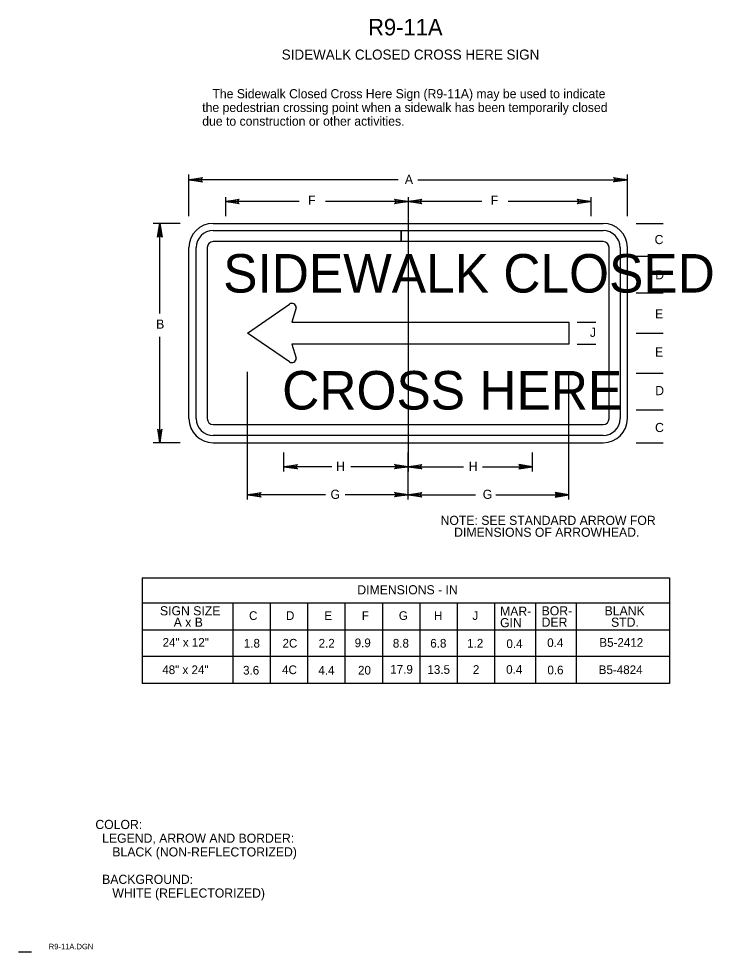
# Model space of a CAD drawing. Extents: x 0.004 to 0.194, y 0.004 to 0.259.
import ezdxf

# ---------------------------------------------------------------- set-up
doc = ezdxf.new("R2010")
doc.units = 0
for name, color, linetype in [('1', 7, 'Continuous'), ('2', 7, 'Continuous'), ('3', 7, 'Continuous'), ('63', 7, 'Continuous')]:
    doc.layers.add(name, color=color, linetype=linetype)

# ---------------------------------------------------------------- blocks, each defined once
blk = doc.blocks.new('RARROW')
at = {"layer": '3'}
for p, q in [((-2.156, 0.28500000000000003), (-2.2665, 0.384625)), ((-2.2665, 0.384625), (0, 0)), ((0, 0), (-2.2665, -0.379125)), ((-2.156, 0.28500000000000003), (-2.075625, 0.12075)), ((0, 0), (-2.156, 0.28500000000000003)), ((-2.14975, -0.2705), (0, 0)), ((-2.075625, 0.12075), (0, 0)), ((0, 0), (-2.074, -0.108)), ((-2.2665, -0.379125), (-2.14975, -0.2705)), ((-2.074, -0.108), (-2.14975, -0.2705))]:
    blk.add_line(p, q, dxfattribs=at)

msp = doc.modelspace()

# ---------------------------------------------------------------- linework, layer by layer
at = {"layer": '1'}
for p, q in [((0.060734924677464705, 0.2103580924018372), (0.060734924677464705, 0.2051699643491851)), ((0.11073492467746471, 0.2103580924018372), (0.11073492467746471, 0.2051699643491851)), ((0.1607349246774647, 0.2103580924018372), (0.1607349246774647, 0.2051699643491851)), ((0.11073492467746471, 0.20747962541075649), (0.11073492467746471, 0.1353943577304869)), ((0.04834544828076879, 0.2032247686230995), (0.040945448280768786, 0.2032247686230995)), ((0.1731244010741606, 0.2032247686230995), (0.18052440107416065, 0.2032247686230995)), ((0.05733492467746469, 0.2012247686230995), (0.10885361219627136, 0.2012247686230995)), ((0.10885361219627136, 0.2012247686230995), (0.10885361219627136, 0.19822476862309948)), ((0.10885361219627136, 0.19822476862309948), (0.10885361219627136, 0.2012247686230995)), ((0.10885361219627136, 0.2012247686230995), (0.16413492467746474, 0.2012247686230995)), ((0.05273492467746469, 0.14982476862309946), (0.05273492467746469, 0.19662476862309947)), ((0.0557349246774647, 0.19662476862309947), (0.0557349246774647, 0.14982476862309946)), ((0.10885361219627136, 0.19822476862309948), (0.05733492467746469, 0.19822476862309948)), ((0.16413492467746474, 0.19822476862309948), (0.10885361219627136, 0.19822476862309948)), ((0.1657349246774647, 0.14982476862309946), (0.1657349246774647, 0.19662476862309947)), ((0.1687349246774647, 0.19662476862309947), (0.1687349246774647, 0.14982476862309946)), ((0.1731244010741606, 0.1942247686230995), (0.18052440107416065, 0.1942247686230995)), ((0.1731244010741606, 0.1842247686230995), (0.18052440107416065, 0.1842247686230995)), ((0.06673492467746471, 0.17322476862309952), (0.07823635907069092, 0.18111449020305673)), ((0.08011521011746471, 0.18012491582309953), (0.07891127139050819, 0.17622483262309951)), ((0.07891127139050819, 0.17622483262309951), (0.15473492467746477, 0.17622483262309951)), ((0.15473492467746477, 0.17622483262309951), (0.15473492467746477, 0.17022470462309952)), ((0.15697181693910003, 0.17622483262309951), (0.16213492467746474, 0.17622483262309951)), ((0.07823635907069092, 0.16533504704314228), (0.06673492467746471, 0.17322476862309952)), ((0.1731244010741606, 0.1732247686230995), (0.18052440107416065, 0.1732247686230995)), ((0.15473492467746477, 0.17022470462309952), (0.07891127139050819, 0.17022470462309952)), ((0.07891127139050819, 0.17022470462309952), (0.08011521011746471, 0.1663246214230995)), ((0.15697181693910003, 0.17022470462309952), (0.16213492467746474, 0.17022470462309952)), ((0.06673492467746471, 0.12773552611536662), (0.06673492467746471, 0.1626601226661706)), ((0.15473492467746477, 0.12773552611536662), (0.15473492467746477, 0.1626601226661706)), ((0.1731244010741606, 0.1622247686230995), (0.18052440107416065, 0.1622247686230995)), ((0.1731244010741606, 0.1522247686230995), (0.18052440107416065, 0.1522247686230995)), ((0.05733492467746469, 0.14822476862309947), (0.16413492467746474, 0.14822476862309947)), ((0.04834544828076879, 0.14322476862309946), (0.040945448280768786, 0.14322476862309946)), ((0.16413492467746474, 0.14522476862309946), (0.05733492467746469, 0.14522476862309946)), ((0.1731244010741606, 0.1432247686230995), (0.18052440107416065, 0.1432247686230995)), ((0.0767349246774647, 0.1353943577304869), (0.0767349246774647, 0.14058248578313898)), ((0.11073492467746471, 0.12773552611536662), (0.11073492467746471, 0.14058248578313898)), ((0.1447349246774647, 0.1353943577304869), (0.1447349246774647, 0.14058248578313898))]:
    msp.add_line(p, q, dxfattribs=at)
for centre, radius, start, end in [((0.05733492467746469, 0.19662476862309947), 0.006600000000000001, 90, 180), ((0.16413492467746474, 0.19662476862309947), 0.006600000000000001, 0, 90), ((0.05733492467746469, 0.19662476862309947), 0.004600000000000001, 90, 180), ((0.16413492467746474, 0.19662476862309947), 0.004600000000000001, 0, 90), ((0.05733492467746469, 0.19662476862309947), 0.0016, 90, 180), ((0.16413492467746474, 0.19662476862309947), 0.0016, 0, 90), ((0.07891518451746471, 0.18012491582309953), 0.0012000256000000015, 360, 124.44923355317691), ((0.07891518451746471, 0.1663246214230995), 0.0012000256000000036, 235.55076644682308, 0), ((0.05733492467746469, 0.14982476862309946), 0.006600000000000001, 180, 270), ((0.05733492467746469, 0.14982476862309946), 0.004600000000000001, 180, 270), ((0.05733492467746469, 0.14982476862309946), 0.0016, 180, 270), ((0.16413492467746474, 0.14982476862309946), 0.006600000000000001, 270, 0), ((0.16413492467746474, 0.14982476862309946), 0.0016, 270, 0), ((0.16413492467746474, 0.14982476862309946), 0.004600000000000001, 270, 0)]:
    msp.add_arc(centre, radius, start, end, dxfattribs=at)
at = {"layer": '3'}
for p, q in [((0.05073492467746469, 0.2051699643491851), (0.05073492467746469, 0.21658827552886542)), ((0.10801355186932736, 0.21515112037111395), (0.05073492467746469, 0.21515112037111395)), ((0.11337122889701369, 0.21515112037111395), (0.1707349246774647, 0.21515112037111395)), ((0.1707349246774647, 0.2051699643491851), (0.1707349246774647, 0.21658827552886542)), ((0.08088761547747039, 0.20921760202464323), (0.0607349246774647, 0.20921760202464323)), ((0.11073492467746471, 0.20921760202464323), (0.08806777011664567, 0.20921760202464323)), ((0.1308876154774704, 0.20921760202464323), (0.1107349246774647, 0.20921760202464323)), ((0.1607349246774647, 0.20921760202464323), (0.13806777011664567, 0.20921760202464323)), ((0.042791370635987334, 0.1785743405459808), (0.042791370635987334, 0.2032247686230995)), ((0.05733492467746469, 0.2032247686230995), (0.16413492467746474, 0.2032247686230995)), ((0.05073492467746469, 0.14982476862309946), (0.05073492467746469, 0.19662476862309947)), ((0.1707349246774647, 0.14982476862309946), (0.1707349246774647, 0.19662476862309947)), ((0.042791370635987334, 0.14322476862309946), (0.042791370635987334, 0.17220035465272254)), ((0.05733492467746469, 0.14322476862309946), (0.16413492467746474, 0.14322476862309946)), ((0.08984825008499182, 0.13667692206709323), (0.0767349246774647, 0.13667692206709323)), ((0.11073492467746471, 0.13667692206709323), (0.09506019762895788, 0.13667692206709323)), ((0.11073492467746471, 0.13667692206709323), (0.1258580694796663, 0.13667692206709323)), ((0.13107001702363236, 0.13667692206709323), (0.1447349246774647, 0.13667692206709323)), ((0.08811093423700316, 0.12901809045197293), (0.06673492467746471, 0.12901809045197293)), ((0.11073492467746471, 0.12901809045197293), (0.09348081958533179, 0.12901809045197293)), ((0.11073492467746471, 0.12901809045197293), (0.1291747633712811, 0.12901809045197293)), ((0.13470258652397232, 0.12901809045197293), (0.15473492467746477, 0.12901809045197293)), ((0.037933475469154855, 0.10626767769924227), (0.037933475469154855, 0.07739267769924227)), ((0.037975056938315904, 0.10626480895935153), (0.18230847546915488, 0.10626480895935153)), ((0.18230847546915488, 0.10626767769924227), (0.18230847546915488, 0.07739554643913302)), ((0.18230847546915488, 0.09939267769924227), (0.037933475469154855, 0.09939267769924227)), ((0.0627250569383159, 0.09938980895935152), (0.0627250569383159, 0.07739267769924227)), ((0.07293347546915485, 0.09939267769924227), (0.07293347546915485, 0.07739267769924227)), ((0.08318347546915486, 0.09939267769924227), (0.08318347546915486, 0.07739267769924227)), ((0.09343347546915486, 0.09939267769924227), (0.09343347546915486, 0.07739267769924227)), ((0.10368347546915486, 0.09939267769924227), (0.10368347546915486, 0.07739267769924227)), ((0.11393347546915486, 0.09939267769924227), (0.11393347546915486, 0.07739267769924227)), ((0.12418347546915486, 0.09939267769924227), (0.12418347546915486, 0.07739267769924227)), ((0.1343918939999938, 0.09939554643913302), (0.1343918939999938, 0.07739554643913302)), ((0.14555847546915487, 0.09939267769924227), (0.14555847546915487, 0.07739554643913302)), ((0.15668347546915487, 0.09939267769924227), (0.15668347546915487, 0.07739554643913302)), ((0.18230847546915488, 0.09201767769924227), (0.037933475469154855, 0.09201767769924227)), ((0.18230847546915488, 0.08476767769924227), (0.037933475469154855, 0.08476767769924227)), ((0.18230847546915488, 0.07739267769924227), (0.037933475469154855, 0.07739267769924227))]:
    msp.add_line(p, q, dxfattribs=at)
at = {"layer": '63'}
msp.add_line((0.007625, 0.003875), (0.004125, 0.003875), dxfattribs=at)

# ---------------------------------------------------------------- block references
at = {"layer": '3', "xscale": 0.001654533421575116}
for p, yscale, rotation in [((0.05073492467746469, 0.21515112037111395), 0.0016366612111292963, 180), ((0.0607349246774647, 0.20921760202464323), 0.0016366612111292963, 180), ((0.1107349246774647, 0.20921760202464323), 0.0016366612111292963, 180), ((0.042791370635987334, 0.2032247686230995), 0.0016366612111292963, 89.99999999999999), ((0.042791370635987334, 0.14322476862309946), -0.0016366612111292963, -89.99999999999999), ((0.0767349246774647, 0.13667692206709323), 0.0016366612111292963, 180), ((0.11073492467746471, 0.13667692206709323), 0.0016366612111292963, 180), ((0.06673492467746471, 0.12901809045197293), 0.0016366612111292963, 180), ((0.11073492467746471, 0.12901809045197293), 0.0016366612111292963, 180)]:
    msp.add_blockref('RARROW', p, dxfattribs=dict(at, yscale=yscale, rotation=rotation))
for p, yscale in [((0.1707349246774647, 0.21515112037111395), 0.0016366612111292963), ((0.11073492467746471, 0.20921760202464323), 0.0016366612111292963), ((0.1607349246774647, 0.20921760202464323), 0.0016366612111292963), ((0.11073492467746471, 0.13667692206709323), 0.0016366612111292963), ((0.1447349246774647, 0.13667692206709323), -0.0016366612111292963), ((0.11073492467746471, 0.12901809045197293), 0.0016366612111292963), ((0.15473492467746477, 0.12901809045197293), -0.0016366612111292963)]:
    msp.add_blockref('RARROW', p, dxfattribs=dict(at, yscale=yscale))

# ---------------------------------------------------------------- texts
at = {"layer": '1'}
for s, height, p in [('R9-11A', 0.0045000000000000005, (0.09976022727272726, 0.254625)), ('SIDEWALK CLOSED CROSS HERE SIGN', 0.00275025, (0.07613663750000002, 0.248)), ('SIDEWALK CLOSED', 0.010528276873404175, (0.060103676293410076, 0.18429092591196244)), ('CROSS HERE', 0.010528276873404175, (0.07624317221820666, 0.15230932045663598)), ('COLOR:', 0.0024997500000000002, (0.025125, 0.03758760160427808)), ('  LEGEND, ARROW AND BORDER:', 0.0024997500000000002, (0.025125, 0.03383785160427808)), ('     BLACK (NON-REFLECTORIZED) ', 0.0024997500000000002, (0.025125, 0.03008810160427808)), ('  BACKGROUND:', 0.0024997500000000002, (0.025125, 0.022588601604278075)), ('     WHITE (REFLECTORIZED)          ', 0.0024997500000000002, (0.025125, 0.018838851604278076)), ('R9-11A.DGN', 0.0015, (0.012361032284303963, 0.004699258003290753))]:
    msp.add_text(s, height=height, dxfattribs=at).set_placement(p)
at = {"layer": '2'}
for s, p in [('   The Sidewalk Closed Cross Here Sign (R9-11A) may be used to indicate', (0.05437122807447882, 0.23742045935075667)), ('the pedestrian crossing point when a sidewalk has been temporarily closed', (0.05437122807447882, 0.23367070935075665)), ('due to construction or other activities.', (0.05437122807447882, 0.22992095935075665))]:
    msp.add_text(s, height=0.0024997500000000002, dxfattribs=at).set_placement(p)
at = {"layer": '3'}
for s, height, p in [('A', 0.0024997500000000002, (0.10983955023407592, 0.2140160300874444)), ('F', 0.0024997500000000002, (0.0833298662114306, 0.20832719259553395)), ('F', 0.0024997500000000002, (0.1333298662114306, 0.20832719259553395)), ('B', 0.0024997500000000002, (0.041760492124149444, 0.1744229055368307)), ('H', 0.0024997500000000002, (0.09102043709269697, 0.13553841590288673)), ('G', 0.0024997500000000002, (0.08948461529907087, 0.12787958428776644)), ('NOTE: SEE STANDARD ARROW FOR', 0.0024997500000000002, (0.11960854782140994, 0.12075197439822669)), ('    DIMENSIONS OF ARROWHEAD.', 0.0024997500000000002, (0.11960854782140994, 0.11750222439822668)), ('DIMENSIONS - IN', 0.0024997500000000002, (0.09682655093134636, 0.1017676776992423)), ('SIGN SIZE', 0.0024997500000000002, (0.04280847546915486, 0.09601767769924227)), ('C', 0.0023752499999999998, (0.06718347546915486, 0.09476767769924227)), ('D', 0.0023752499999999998, (0.07730847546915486, 0.09476767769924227)), ('E', 0.0023752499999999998, (0.08780847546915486, 0.09476767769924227)), ('F', 0.0023752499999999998, (0.09805847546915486, 0.09476767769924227)), ('G', 0.0023752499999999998, (0.10818347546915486, 0.09476767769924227)), ('J', 0.0023752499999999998, (0.1283102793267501, 0.09476767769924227)), ('MAR-', 0.0024997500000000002, (0.1358918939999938, 0.09589554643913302)), ('BOR-', 0.0024997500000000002, (0.14726689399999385, 0.09602054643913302)), ('BLANK', 0.0024997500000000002, (0.16451689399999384, 0.09602054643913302)), ('A x B', 0.0024997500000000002, (0.046558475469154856, 0.09289267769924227)), ('GIN', 0.0024997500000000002, (0.1358918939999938, 0.09277054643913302)), ('DER', 0.0024997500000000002, (0.14726689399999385, 0.09289554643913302)), ('STD.', 0.0024997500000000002, (0.16626689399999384, 0.09289554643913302)), ('24" x 12"', 0.0023752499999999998, (0.043519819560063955, 0.08745505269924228)), ('1.8', 0.0023752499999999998, (0.06575496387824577, 0.08720505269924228)), ('2C', 0.0023752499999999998, (0.0763480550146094, 0.08720505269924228)), ('2.2', 0.0023752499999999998, (0.08622845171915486, 0.08720505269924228)), ('9.9', 0.0023752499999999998, (0.09608807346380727, 0.08730719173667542)), ('8.8', 0.0023752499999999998, (0.10653903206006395, 0.08720505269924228)), ('1.2', 0.0023752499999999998, (0.12687806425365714, 0.08720505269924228)), ('0.4', 0.0023752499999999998, (0.13762389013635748, 0.08708292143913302)), ('0.4', 0.0023752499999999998, (0.14879600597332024, 0.0873580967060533)), ('B5-2412', 0.0023752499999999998, (0.16307285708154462, 0.08741594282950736)), ('48" x 24"', 0.0023752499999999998, (0.04342888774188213, 0.07995505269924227)), ('3.6', 0.0023752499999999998, (0.06555198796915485, 0.07983005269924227)), ('4C', 0.0023752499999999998, (0.07622305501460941, 0.07995505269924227)), ('4.4', 0.0023752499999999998, (0.08616547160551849, 0.07983005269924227)), ('20', 0.0023752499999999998, (0.09701480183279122, 0.07983005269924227)), ('17.9', 0.0023752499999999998, (0.1058358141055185, 0.08008005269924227)), ('13.5', 0.0023752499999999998, (0.11601657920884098, 0.08002501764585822)), ('0.4', 0.0023752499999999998, (0.13756885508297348, 0.08003843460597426)), ('0.6', 0.0023752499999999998, (0.14884546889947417, 0.079888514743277)), ('B5-4824', 0.0023752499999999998, (0.16289608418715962, 0.07995979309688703))]:
    msp.add_text(s, height=height, dxfattribs=at).set_placement(p)
for s, height, p in [('C', 0.0024997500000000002, (0.17819412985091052, 0.19754487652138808)), ('D', 0.0024997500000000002, (0.17837896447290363, 0.1879067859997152)), ('E', 0.0024997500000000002, (0.17831867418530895, 0.17722307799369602)), ('J', 0.0024997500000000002, (0.16048314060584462, 0.17218488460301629)), ('E', 0.0024997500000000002, (0.17831867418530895, 0.16679116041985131)), ('D', 0.0024997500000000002, (0.17834904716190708, 0.15623316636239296)), ('C', 0.0024997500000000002, (0.17831379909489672, 0.14614631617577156)), ('H', 0.0024997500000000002, (0.127323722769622, 0.13553841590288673)), ('G', 0.0024997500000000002, (0.13115778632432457, 0.12787958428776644)), ('H', 0.0023752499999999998, (0.11780306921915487, 0.09476767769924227)), ('6.8', 0.0023752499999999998, (0.11678903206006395, 0.08720505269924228)), ('2', 0.0023752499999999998, (0.12845007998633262, 0.08002501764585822))]:
    msp.add_text(s, height=height, rotation=360, dxfattribs=at).set_placement(p)

doc.saveas('drawing.dxf')
